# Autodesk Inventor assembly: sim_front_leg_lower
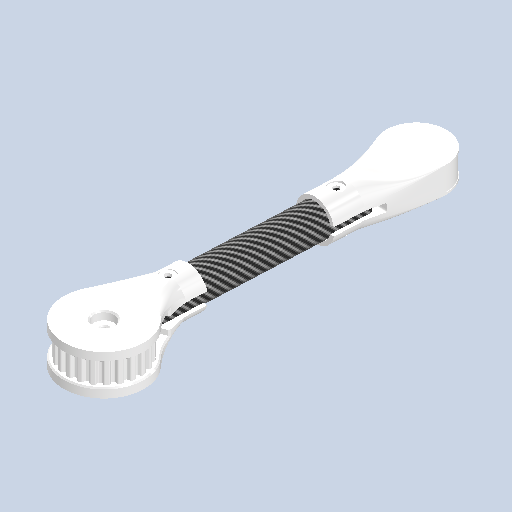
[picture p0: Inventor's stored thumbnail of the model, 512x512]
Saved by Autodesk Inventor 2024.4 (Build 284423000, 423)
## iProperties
Created: 2026-01
Part Number: sim_front_leg_lower
Document SubType Name: Assembly
Designer: AdminForWorker
Title: front_leg_lower v2
Author: AdminForWorker
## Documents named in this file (4)
- c:\worker\convert-fusion-r06-cosv3\tmp\job-1\18\temp\files\2b8cab70-cf69-4890-a216-e9828dcc6452\71dca5f5-5527-4425-b02e-3953da9594ae.iam
- c:\worker\convert-fusion-r06-cosv3\tmp\job-1\18\temp\files\2b8cab70-cf69-4890-a216-e9828dcc6452\foot.ipt
- c:\worker\convert-fusion-r06-cosv3\tmp\job-1\18\temp\files\2b8cab70-cf69-4890-a216-e9828dcc6452\knee.ipt
- c:\worker\convert-fusion-r06-cosv3\tmp\job-1\18\temp\files\2b8cab70-cf69-4890-a216-e9828dcc6452\carbon_fiber_tube.ipt
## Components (3 placed, 3 different names)
1. foot:1
2. knee:1
3. carbon_fiber_tube:1
